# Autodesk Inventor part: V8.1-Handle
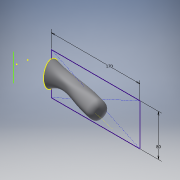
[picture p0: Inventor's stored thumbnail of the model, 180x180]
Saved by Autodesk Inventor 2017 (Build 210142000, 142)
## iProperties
Created: 2015-10
Part Number: V8.1-Handle
Material: Generic
Document SubType Name: Modeling
Designer: Luke Denby
Density: 1 g/cm^3
Appearance: Default
Author: Luke Denby
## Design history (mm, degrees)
workplane "Work Plane3"
sketch "Front"
  geometry: L1 (15, -25)-(-15, -25); L2 (-15, -25)-(-15, 25); L3 (-15, 25)-(15, 25); L4 (15, 25)-(15, -25); L5 (0, -25)-(0, 25); L6 (-15, 0)-(15, 0); 2 further points
  constraints: 12 end point, 6 midpoint, 2 parallel, 2 perpendicular, 1 coincident, 1 horizontal, 4 other
  dimensions: "d3" = 30 distance of L6.start L6.end; "d8" = 50 distance of L5.start L5.end
sketch "End" dims "d15" = 8, "d16" = 8
  geometry: L1 (10, 17)-(10, -13); L2 (24, 0)-(-0.308, 0); 6 further points; 1 other entity
  constraints: 4 end point, 4 point on line, 1 horizontal, 1 vertical, 6 other
sketch "Sides" dims "d40" = 16 (derived)
sketch "Top"
node "3D Sketch8"
sketch "Bottom"
loft "Loft1" sketch "Bottom" dims "d17" = 0, "d18" = 90 deg, "d19" = 0, "d20" = 90 deg, "d21" = 0, "d22" = 90 deg, "d23" = 0, "d24" = 90 deg, "d25" = 0, "d26" = 90 deg, "d53" = 0, "d54" = 90 deg
fillet "Fillet3" dims "d29" = 6
sketch "Angle Line"
  geometry: L1 (151, -33)-(0, 0)
  constraints: 2 end point
workplane "Work Plane8"
node "3D Sketch11"
sketch "Sketch14"
  geometry: L1 (-1.282, 2.515)-(1.536, 2.515); L2 (1.536, 2.515)-(1.536, -1.569); L3 (1.536, -1.569)-(-1.282, -1.569); L4 (-1.282, -1.569)-(-1.282, 2.515); 1 further point
  constraints: 2 other
extrude "Version Number" cut sketch "Sketch14" distance "d57" = 2; taper "d58" = 0 deg
sketch "Sketch16"
  geometry: 1 further point
workplane "Work Plane10"
sketch "Sketch20"
  geometry: L1 (-24, -28)-(28, -28); 1 further point
  constraints: 2 end point, 1 horizontal
workplane "Work Plane11"
sketch "Sketch25"
  geometry: 1 further point
sketch "Clip Front"
  geometry: L1 (9, 10.92)-(39, 10.92); L2 (24, 23.42)-(24, -1.58); 4 further points
  constraints: 4 end point, 3 midpoint, 1 coincident, 1 horizontal, 1 point on line, 1 vertical, 7 other
  dimensions: "d73" = 30 distance of L1.start point (39, 10.92); "d74" = 25 distance of L2.end L2.start
sketch "Clip Sides"
sketch "Clip Top"
  geometry: L1 (0, 15)-(-29, 5); L2 (-29, 5)-(-53.01, -5.992); L3 (-53.01, -5.992)-(-44.46, -29.484) reference; 2 further points
  constraints: 1 coincident, 3 other
sketch "Sketch24"
  geometry: L1 (0, 15)-(0, -15); 1 further point
  constraints: 2 end point, 1 vertical, 1 vertical alignment, 1 other
sketch "Clip Bottom"
  geometry: L1 (0, -15)-(-26, -26); L2 (-26, -26)-(-44.46, -29.484); L3 (0, 15)-(0, -15) reference; 2 further points
  constraints: 1 coincident, 3 other
loft "Clip" sketch "Clip Bottom" dims "d75" = 0, "d76" = 90 deg, "d77" = 0, "d78" = 90 deg, "d79" = 0, "d80" = 90 deg, "d81" = 0, "d82" = 90 deg, "d83" = 0, "d84" = 90 deg, "d85" = 0, "d86" = 90 deg
  node "Edges1"
workplane "Work Plane12"
sketch "Clip Hole Sketch"
  geometry: L1 (39, 0)-(9, 0) reference; L2 (24, -194.931)-(24, 89.069); L3 (14, 8.268)-(14, -26.732); L4 (34, 8.268)-(34, -26.732); A1 r 10 centre (24, -26.732) between (24, -36.732) and (14, -26.732); A2 r 10 centre (24, 8.268) between (24, 18.268) and (14, 8.268); 6 further points
  constraints: 6 end point, 6 point on circle, 6 point on line, 4 tangent, 2 centre point, 1 midpoint, 1 vertical, 2 other
  dimensions: "d88" = 20 diameter of A1; "d141" = 20 diameter of A2; "d142" = 55 distance of A2.start A1.start; "d145" = 20 distance of A1.centre point (24, -46.732)
sketch "Sketch27"
  geometry: C1 r 2.25 at (0, -12); C2 r 2.25 at (0, 12); 1 further point
  constraints: 2 centre point, 2 vertical alignment
  dimensions: "d93" = 4.5 diameter of C1; "d94" = 4.5 diameter of C2; "d95" = 12 distance of point (0, 0) C1.centre; "d96" = 12 distance of point (0, 0) C2.centre
extrude "Screw Holes Handle" cut sketch "Sketch27" distance "d97" = 12; taper "d99" = 0 deg; dims "d98" = 20, "d100" = 0
node "Counterbore Workplane"
sketch "Sketch28"
  geometry: C1 r 4.5 at (0, -12); C2 r 4.5 at (0, 12); 1 further point
  constraints: 2 centre point, 2 vertical alignment
  dimensions: "d102" = 9 diameter of C2; "d103" = 12 distance of point (0, 0) C1.centre; "d104" = 12 distance of C2.centre point (0, 0); "d128" = 9 diameter of C1
extrude "Counterbore" cut sketch "Sketch28" distance "d105" = 15; taper "d106" = 0 deg
sketch "Sketch29"
  geometry: C1 r 2.5 at (0, -12); C2 r 2.25 at (0, 12) reference; C3 r 2.5 at (0, 12); 1 further point
  constraints: 2 centre point, 2 vertical alignment
  dimensions: "d107" = 5 diameter of C1; "d108" = 5 diameter of C3; "d109" = 12 distance of point (0, 0) C1.centre; "d131" = 12 distance of C3.centre point (0, 0)
extrude "Screw Holes Clip" cut sketch "Sketch29" stored distance "d110" = 20; taper "d111" = 0 deg
workplane "Work Plane14"
fillet "Fillet8" dims "d125" = 4
extrude "Clip Hole" cut sketch "Clip Hole Sketch" stored distance "d143" = 10; taper "d144" = 0 deg
fillet "Fillet14" dims "d146" = 1
sketch "Handle Cut Off Sketch"
  geometry: L1 (-170, -40)-(0, -40); L2 (0, -40)-(0, 40); L3 (0, 40)-(-170, 40); L4 (-170, 40)-(-170, -40); L5 (-170, -40)-(0, 40); L6 (0, -40)-(-170, 40); 4 further points
  constraints: 12 end point, 3 midpoint, 2 parallel, 1 horizontal, 1 horizontal alignment, 1 perpendicular, 1 point on line
  dimensions: "d112" = 80 distance of L3.end L1.start; "d113" = 170 distance of L2.end L3.end
sketch "Clip Cut Off Sketch"
  geometry: L1 (74, 41)-(0, 41); L2 (0, 41)-(0, -41); L3 (0, -41)-(74, -41); L4 (74, -41)-(74, 41); L5 (74, 41)-(0, -41); L6 (0, 41)-(74, -41); L7 (-165.272, 0)-(74, 0); L8 (-170, -40)-(0, -40) reference; L9 (0, -40)-(0, 40) reference; 4 further points
  constraints: 14 end point, 4 midpoint, 2 parallel, 1 horizontal, 1 perpendicular, 1 point on line
  dimensions: "d133" = 74 distance of L2.end L3.end; "d134" = 82 distance of L3.end L1.start; "d136" = 40 distance between parallel lines of L7 L8
workplane "Work Plane15"
workplane "Work Plane16"
sketch "Slot Top"
  geometry: L1 (24, -207.167)-(24, 17.675) reference; L2 (38.5, -26.732)-(9.5, -26.732); L3 (38.5, -15.732)-(9.5, -15.732); L4 (38.5, -26.732)-(38.5, -15.732); L5 (9.5, -26.732)-(9.5, -15.732); A1 r 14.5 centre (24, -26.732) between (9.5, -26.732) and (38.5, -26.732); A2 r 14.5 centre (24, -15.732) between (38.5, -15.732) and (9.5, -15.732); 1 further point
  constraints: 8 end point, 4 point on circle, 2 centre point, 2 midpoint, 1 horizontal, 1 perpendicular, 1 point on line
  dimensions: "d154" = 29 diameter of A2; "d155" = 29 diameter of A1; "d156" = 40 dimension on A2 A1
sketch "Slot Bottom"
  geometry: L1 (24, -42.982)-(24, 3.018); L2 (7.75, -26.732)-(7.75, -13.232); L3 (7.75, -26.732)-(39.868, -26.732); L4 (7.75, -13.232)-(40.25, -13.232); L5 (40.25, -26.732)-(40.25, -13.232); A1 r 16.25 centre (24, -26.732) between (7.75, -26.732) and (40.25, -26.732); A2 r 16.25 centre (24, -13.232) between (40.25, -13.232) and (7.75, -13.232); 2 further points
  constraints: 10 end point, 6 point on circle, 3 point on line, 2 centre point, 2 horizontal, 2 tangent, 1 coincident, 1 vertical, 1 vertical alignment
  dimensions: "d157" = 32.5 diameter of A1; "d158" = 32.5 diameter of A2; "d159" = 46 distance of L1.end L1.start
loft "Bottle Slot" sketch "Slot Top", "Slot Bottom" dims "d160" = 0, "d161" = 90 deg, "d162" = 0, "d163" = 90 deg
fillet "Fillet16" dims "d164" = 1
sketch "Sketch39"
  geometry: C1 r 34.655 at (0, 0); 1 further point
  constraints: 1 centre point
extrude "Extrusion18" cut sketch "Sketch39" distance "d170" = 40; taper "d171" = 0 deg
fillet "Fillet17" dims "d172" = 10
extrude "Extrusion19" cut sketch "Clip Cut Off Sketch" stored distance "d173" = 0; taper "d174" = 0 deg
body "Solid2"
other parameters: "d46" = 90 deg, "d69" = 45, "d72" = 20 deg, "d87" = 90 deg, "d152" = 8, "d153" = -26
